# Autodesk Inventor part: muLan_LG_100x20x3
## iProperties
Shininess: 64.0
Length Units: 11269
Angle Units: 11279
Time Units: 11290
Mass Units: 11283
Length Display Precision: 3
Angle Display Precision: 2
Compacted: True
Part Number: muLan_LG_100x20x3
Document SubType Name: Modeling
Created: 2004-08
Designer: John Blackburn
Manufacturer: Standard
Standards Organization: Custom
Material: Lexan, Clear
Density: 0.0
Volumn: 0.0
Area: 0.0
PropertySet Name: Model Information
Control State: 0
Master: False
Checked Out: False
Author: John Blackburn
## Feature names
1. Loft1
2. Extrusion1
